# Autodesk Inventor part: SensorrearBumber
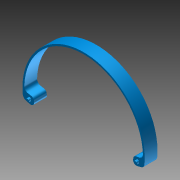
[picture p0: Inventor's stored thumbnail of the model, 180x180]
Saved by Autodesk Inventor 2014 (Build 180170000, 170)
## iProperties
Created: 2015-06
Part Number: SensorrearBumber
Material: Generic
Document SubType Name: Modeling
Designer: common
Density: 1 g/cm^3
Appearance: Default
Author: common
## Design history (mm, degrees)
node "SensorrearBumber.ipt1"
body "Solid2"
node "Base1"
